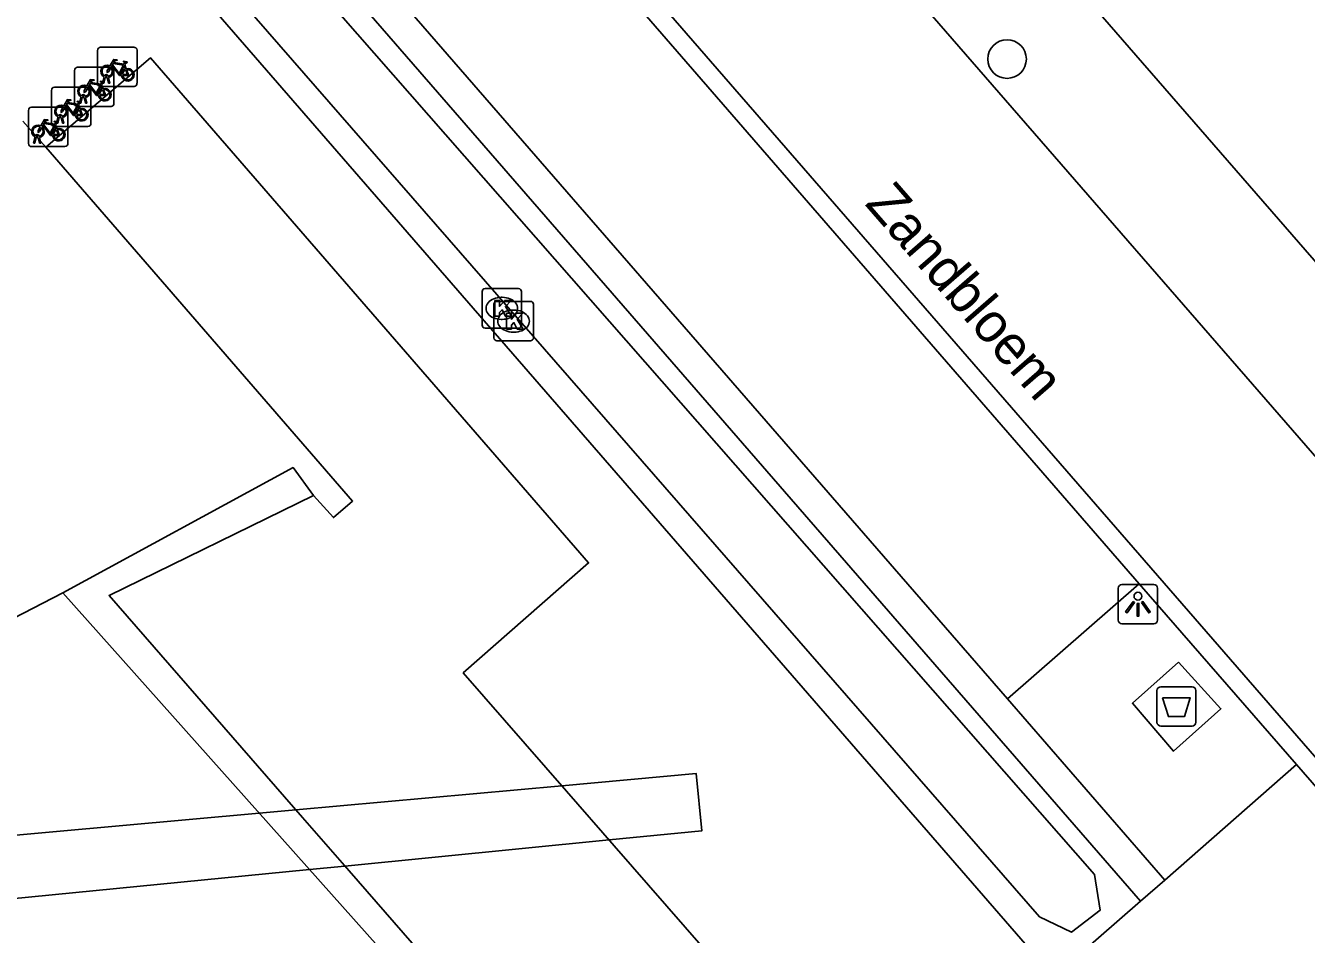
# Model space of a CAD drawing. Extents: x 155888 to 156864, y 383882 to 384671.
# Drawn here: x 156308.74 to 156341.24, y 384016.55 to 384039.61 of the extents above; entities that cross this region are included whole.
import ezdxf

# ---------------------------------------------------------------- set-up
doc = ezdxf.new("R2010")
doc.units = 0
for name, color, linetype in [('IMGEO_Afval_apart_plaats', 7, 'Continuous'), ('IMGEO_Boom', 7, 'Continuous'), ('IMGEO_Dek', 7, 'Continuous'), ('IMGEO_Fietsenrek', 7, 'Continuous'), ('IMGEO_Greppel_droge_sloot', 7, 'Continuous'), ('IMGEO_Kolk', 7, 'Continuous'), ('IMGEO_Lichtpunt', 7, 'Continuous'), ('IMGEO_Muur', 7, 'Continuous'), ('IMGEO_Openbare_ruimte_label', 7, 'Continuous'), ('IMGEO_Pand', 7, 'Continuous'), ('IMGEO_Rijbaan_lokaal_gesloten', 7, 'Continuous'), ('IMGEO_Rijbaan_lokaal_open', 7, 'Continuous'), ('IMGEO_Voetpad_gesloten', 7, 'Continuous'), ('IMGEO_Voetpad_op_trap', 7, 'Continuous'), ('IMGEO_Voetpad_open', 7, 'Continuous')]:
    doc.layers.add(name, color=color, linetype=linetype)

msp = doc.modelspace()

# ---------------------------------------------------------------- linework, layer by layer
at = {"layer": 'IMGEO_Afval_apart_plaats'}
for p, q in [((156337.444, 384021.934), (156337.444, 384022.734)), ((156337.444, 384022.734), (156337.444, 384021.934)), ((156337.544, 384022.834), (156338.334, 384022.834)), ((156338.334, 384022.834), (156337.544, 384022.834)), ((156338.434, 384022.734), (156338.434, 384021.934)), ((156338.434, 384021.934), (156338.434, 384022.734)), ((156338.334, 384021.834), (156337.544, 384021.834)), ((156337.544, 384021.834), (156338.334, 384021.834))]:
    msp.add_line(p, q, dxfattribs=at)
msp.add_lwpolyline([(156337.587, 384022.548), (156338.291, 384022.548), (156338.142, 384022.078), (156337.736, 384022.078), (156337.587, 384022.548)], dxfattribs=at)
for centre, start, end in [((156337.544, 384022.734), 90, 180), ((156337.544, 384022.734), 90, 180), ((156338.334, 384022.734), 0, 90), ((156338.334, 384022.734), 360, 90), ((156337.544, 384021.934), 180, 270), ((156337.544, 384021.934), 180, 270), ((156338.334, 384021.934), 270, 0), ((156338.334, 384021.934), 270, 0)]:
    msp.add_arc(centre, 0.1, start, end, dxfattribs=at)
at = {"layer": 'IMGEO_Boom'}
msp.add_circle((156333.642, 384038.757), 0.489, dxfattribs=at)
at = {"layer": 'IMGEO_Dek'}
msp.add_lwpolyline([(156307.645, 384018.989), (156307.772, 384017.39), (156315.941, 384018.196), (156316.839, 384018.284), (156323.542, 384018.946), (156325.9, 384019.178), (156325.757, 384020.632), (156322.341, 384020.322), (156315.596, 384019.71), (156314.665, 384019.626)], close=True, dxfattribs=at)
at = {"layer": 'IMGEO_Fietsenrek'}
for p, q in [((156310.566, 384038.133), (156310.566, 384038.974)), ((156310.566, 384038.974), (156310.566, 384038.133)), ((156310.641, 384039.058), (156311.482, 384039.058)), ((156311.482, 384039.058), (156310.641, 384039.058)), ((156311.566, 384038.983), (156311.566, 384038.142)), ((156311.566, 384038.142), (156311.566, 384038.983)), ((156309.982, 384037.626), (156309.982, 384038.467)), ((156309.982, 384038.467), (156309.982, 384037.626)), ((156310.057, 384038.551), (156310.898, 384038.551)), ((156310.898, 384038.551), (156310.057, 384038.551)), ((156310.982, 384038.476), (156310.982, 384037.635)), ((156310.982, 384037.635), (156310.982, 384038.476)), ((156311.253, 384038.607), (156311.289, 384038.512)), ((156310.693, 384038.142), (156310.732, 384038.302)), ((156310.727, 384038.142), (156310.693, 384038.142)), ((156310.762, 384038.29), (156310.727, 384038.142)), ((156310.804, 384038.314), (156310.803, 384038.318)), ((156310.845, 384038.142), (156310.811, 384038.284)), ((156310.835, 384038.325), (156310.836, 384038.318)), ((156310.843, 384038.288), (156310.878, 384038.142)), ((156310.878, 384038.142), (156310.845, 384038.142)), ((156309.397, 384037.119), (156309.397, 384037.96)), ((156309.397, 384037.96), (156309.397, 384037.119)), ((156309.472, 384038.044), (156310.313, 384038.044)), ((156310.313, 384038.044), (156309.472, 384038.044)), ((156310.251, 384037.818), (156310.252, 384037.811)), ((156310.397, 384037.969), (156310.397, 384037.128)), ((156310.397, 384037.128), (156310.397, 384037.969)), ((156311.491, 384038.058), (156310.65, 384038.058)), ((156310.65, 384038.058), (156311.491, 384038.058)), ((156310.669, 384038.1), (156310.705, 384038.005)), ((156308.888, 384037.537), (156309.729, 384037.537)), ((156309.729, 384037.537), (156308.888, 384037.537)), ((156310.907, 384037.551), (156310.066, 384037.551)), ((156310.066, 384037.551), (156310.907, 384037.551)), ((156310.084, 384037.593), (156310.12, 384037.498)), ((156310.109, 384037.635), (156310.148, 384037.795)), ((156310.143, 384037.635), (156310.109, 384037.635)), ((156310.178, 384037.783), (156310.143, 384037.635)), ((156310.22, 384037.807), (156310.219, 384037.811)), ((156310.261, 384037.635), (156310.227, 384037.777)), ((156310.259, 384037.781), (156310.294, 384037.635)), ((156310.294, 384037.635), (156310.261, 384037.635)), ((156308.813, 384036.612), (156308.813, 384037.453)), ((156308.813, 384037.453), (156308.813, 384036.612)), ((156309.524, 384037.128), (156309.563, 384037.288)), ((156309.593, 384037.276), (156309.558, 384037.128)), ((156309.635, 384037.3), (156309.634, 384037.304)), ((156309.676, 384037.128), (156309.642, 384037.27)), ((156309.666, 384037.311), (156309.667, 384037.304)), ((156309.674, 384037.274), (156309.709, 384037.128)), ((156309.813, 384037.462), (156309.813, 384036.621)), ((156309.813, 384036.621), (156309.813, 384037.462)), ((156310.322, 384037.044), (156309.481, 384037.044)), ((156309.481, 384037.044), (156310.322, 384037.044)), ((156309.5, 384037.086), (156309.536, 384036.991)), ((156309.558, 384037.128), (156309.524, 384037.128)), ((156309.709, 384037.128), (156309.676, 384037.128)), ((156309.738, 384036.537), (156308.897, 384036.537)), ((156308.897, 384036.537), (156309.738, 384036.537)), ((156308.94, 384036.621), (156308.979, 384036.781)), ((156308.974, 384036.621), (156308.94, 384036.621)), ((156309.009, 384036.769), (156308.974, 384036.621)), ((156309.051, 384036.793), (156309.05, 384036.797)), ((156309.092, 384036.621), (156309.058, 384036.763)), ((156309.082, 384036.804), (156309.083, 384036.797)), ((156309.09, 384036.767), (156309.125, 384036.621)), ((156309.125, 384036.621), (156309.092, 384036.621))]:
    msp.add_line(p, q, dxfattribs=at)
for points in [[(156310.9, 384038.532), (156310.848, 384038.442), (156310.808, 384038.417), (156310.809, 384038.464), (156310.864, 384038.558)], [(156310.879, 384038.584), (156310.974, 384038.748), (156311.06, 384038.734), (156311.062, 384038.725), (156311.006, 384038.714), (156310.979, 384038.669), (156311.235, 384038.628)], [(156311.175, 384038.34), (156311.125, 384038.34), (156310.934, 384038.591), (156310.915, 384038.559)], [(156311.222, 384038.603), (156310.965, 384038.644), (156310.948, 384038.615), (156311.115, 384038.395), (156311.222, 384038.603)], [(156311.27, 384038.505), (156311.24, 384038.582), (156311.131, 384038.364), (156311.174, 384038.364)], [(156311.204, 384038.364), (156311.324, 384038.363), (156311.28, 384038.477)], [(156311.3, 384038.484), (156311.355, 384038.339), (156311.205, 384038.339)], [(156311.235, 384038.628), (156311.26, 384038.677), (156311.254, 384038.681), (156311.231, 384038.685), (156311.219, 384038.692), (156311.218, 384038.695), (156311.22, 384038.7), (156311.315, 384038.685), (156311.317, 384038.675), (156311.307, 384038.662), (156311.295, 384038.656), (156311.281, 384038.662), (156311.253, 384038.607)], [(156310.295, 384038.077), (156310.39, 384038.241), (156310.476, 384038.227), (156310.478, 384038.218), (156310.422, 384038.207), (156310.395, 384038.162), (156310.651, 384038.121)], [(156310.651, 384038.121), (156310.676, 384038.17), (156310.67, 384038.174), (156310.647, 384038.178), (156310.635, 384038.185), (156310.634, 384038.188), (156310.636, 384038.193), (156310.731, 384038.178), (156310.733, 384038.168), (156310.723, 384038.155), (156310.711, 384038.149), (156310.697, 384038.155), (156310.669, 384038.1)], [(156310.316, 384038.025), (156310.264, 384037.935), (156310.224, 384037.91), (156310.225, 384037.957), (156310.28, 384038.051)], [(156310.591, 384037.833), (156310.541, 384037.833), (156310.35, 384038.084), (156310.331, 384038.052)], [(156310.638, 384038.096), (156310.381, 384038.137), (156310.364, 384038.108), (156310.531, 384037.888), (156310.638, 384038.096)], [(156310.686, 384037.998), (156310.656, 384038.075), (156310.547, 384037.857), (156310.59, 384037.857)], [(156310.62, 384037.857), (156310.74, 384037.856), (156310.696, 384037.97)], [(156310.716, 384037.977), (156310.771, 384037.832), (156310.621, 384037.832)], [(156309.731, 384037.518), (156309.679, 384037.428), (156309.639, 384037.403), (156309.64, 384037.45), (156309.695, 384037.544)], [(156309.71, 384037.57), (156309.805, 384037.734), (156309.891, 384037.72), (156309.893, 384037.711), (156309.837, 384037.7), (156309.81, 384037.655), (156310.066, 384037.614)], [(156310.006, 384037.326), (156309.956, 384037.326), (156309.765, 384037.577), (156309.746, 384037.545)], [(156310.053, 384037.589), (156309.796, 384037.63), (156309.779, 384037.601), (156309.946, 384037.381), (156310.053, 384037.589)], [(156310.101, 384037.491), (156310.071, 384037.568), (156309.962, 384037.35), (156310.005, 384037.35)], [(156310.066, 384037.614), (156310.091, 384037.663), (156310.085, 384037.667), (156310.062, 384037.671), (156310.05, 384037.678), (156310.049, 384037.681), (156310.051, 384037.686), (156310.146, 384037.671), (156310.148, 384037.661), (156310.138, 384037.648), (156310.126, 384037.642), (156310.112, 384037.648), (156310.084, 384037.593)], [(156309.126, 384037.063), (156309.221, 384037.227), (156309.307, 384037.213), (156309.309, 384037.204), (156309.253, 384037.193), (156309.226, 384037.148), (156309.482, 384037.107)], [(156309.482, 384037.107), (156309.507, 384037.156), (156309.501, 384037.16), (156309.478, 384037.164), (156309.466, 384037.171), (156309.465, 384037.174), (156309.467, 384037.179), (156309.562, 384037.164), (156309.564, 384037.154), (156309.554, 384037.141), (156309.542, 384037.135), (156309.528, 384037.141), (156309.5, 384037.086)], [(156310.035, 384037.35), (156310.155, 384037.349), (156310.111, 384037.463)], [(156310.131, 384037.47), (156310.186, 384037.325), (156310.036, 384037.325)], [(156309.147, 384037.011), (156309.095, 384036.921), (156309.055, 384036.896), (156309.056, 384036.943), (156309.111, 384037.037)], [(156309.422, 384036.819), (156309.372, 384036.819), (156309.181, 384037.07), (156309.162, 384037.038)], [(156309.469, 384037.082), (156309.212, 384037.123), (156309.195, 384037.094), (156309.362, 384036.874), (156309.469, 384037.082)], [(156309.517, 384036.984), (156309.487, 384037.061), (156309.378, 384036.843), (156309.421, 384036.843)], [(156309.451, 384036.843), (156309.571, 384036.842), (156309.527, 384036.956)], [(156309.547, 384036.963), (156309.602, 384036.818), (156309.452, 384036.818)]]:
    msp.add_lwpolyline(points, dxfattribs=at)
for centre, radius, start, end in [((156310.644, 384038.98), 0.0779, 92.4484, 184.2845), ((156310.644, 384038.98), 0.0779, 92.4484, 184.2845), ((156311.488, 384038.98), 0.0779, 2.4484, 94.2845), ((156311.488, 384038.98), 0.0779, 2.4484, 94.2845), ((156310.06, 384038.473), 0.0779, 92.4484, 184.2845), ((156310.06, 384038.473), 0.0779, 92.4484, 184.2845), ((156310.806, 384038.443), 0.159, 62.6766, 242.1369), ((156310.806, 384038.443), 0.129, 63.3192, 238.903), ((156310.806, 384038.443), 0.129, 283.6043, 43.4302), ((156310.806, 384038.443), 0.159, 283.5766, 46.6042), ((156310.904, 384038.473), 0.0779, 2.4484, 94.2845), ((156310.904, 384038.473), 0.0779, 2.4484, 94.2845), ((156311.333, 384038.359), 0.159, 113.3408, 178.3217), ((156311.333, 384038.359), 0.159, 187.0065, 105.7708), ((156311.333, 384038.359), 0.129, 113.923, 177.9556), ((156311.333, 384038.359), 0.129, 188.6715, 104.5883), ((156310.786, 384038.314), 0.0499, 12.8025, 158.6934), ((156310.806, 384038.443), 0.159, 253.9967, 271.7867), ((156310.786, 384038.314), 0.0174, 12.8025, 163.4502), ((156310.806, 384038.443), 0.129, 253.415, 269.0204), ((156311.488, 384038.136), 0.0779, 272.4484, 4.2845), ((156311.488, 384038.136), 0.0779, 272.4484, 4.2845), ((156309.475, 384037.966), 0.0779, 92.4484, 184.2845), ((156309.475, 384037.966), 0.0779, 92.4484, 184.2845), ((156310.222, 384037.936), 0.159, 62.6766, 242.1369), ((156310.222, 384037.936), 0.129, 63.3192, 238.903), ((156310.202, 384037.807), 0.0499, 12.8025, 158.6934), ((156310.202, 384037.807), 0.0174, 12.8025, 163.4502), ((156310.222, 384037.936), 0.129, 283.6043, 43.4302), ((156310.222, 384037.936), 0.159, 283.5766, 46.6042), ((156310.319, 384037.966), 0.0779, 2.4484, 94.2845), ((156310.319, 384037.966), 0.0779, 2.4484, 94.2845), ((156310.644, 384038.136), 0.0779, 182.4484, 274.2845), ((156310.644, 384038.136), 0.0779, 182.4484, 274.2845), ((156310.749, 384037.852), 0.159, 113.3408, 178.3217), ((156310.749, 384037.852), 0.159, 187.0065, 105.7708), ((156310.749, 384037.852), 0.129, 113.923, 177.9556), ((156310.749, 384037.852), 0.129, 188.6715, 104.5883), ((156308.891, 384037.459), 0.0779, 92.4484, 184.2845), ((156308.891, 384037.459), 0.0779, 92.4484, 184.2845), ((156309.637, 384037.429), 0.159, 62.6766, 242.1369), ((156309.637, 384037.429), 0.129, 63.3192, 238.903), ((156309.637, 384037.429), 0.129, 283.6043, 43.4302), ((156309.637, 384037.429), 0.159, 283.5766, 46.6042), ((156309.735, 384037.459), 0.0779, 2.4484, 94.2845), ((156309.735, 384037.459), 0.0779, 2.4484, 94.2845), ((156310.06, 384037.629), 0.0779, 182.4484, 274.2845), ((156310.06, 384037.629), 0.0779, 182.4484, 274.2845), ((156310.164, 384037.345), 0.159, 113.3408, 178.3217), ((156310.164, 384037.345), 0.159, 187.0065, 105.7708), ((156310.222, 384037.936), 0.159, 253.9967, 271.7867), ((156310.222, 384037.936), 0.129, 253.415, 269.0204), ((156310.904, 384037.629), 0.0779, 272.4484, 4.2845), ((156310.904, 384037.629), 0.0779, 272.4484, 4.2845), ((156309.617, 384037.3), 0.0499, 12.8025, 158.6934), ((156309.637, 384037.429), 0.159, 253.9967, 271.7867), ((156309.617, 384037.3), 0.0174, 12.8025, 163.4502), ((156309.637, 384037.429), 0.129, 253.415, 269.0204), ((156310.164, 384037.345), 0.129, 113.923, 177.9556), ((156310.164, 384037.345), 0.129, 188.6715, 104.5883), ((156309.053, 384036.922), 0.159, 62.6766, 242.1369), ((156309.053, 384036.922), 0.129, 63.3192, 238.903), ((156309.033, 384036.793), 0.0499, 12.8025, 158.6934), ((156309.053, 384036.922), 0.129, 283.6043, 43.4302), ((156309.053, 384036.922), 0.159, 283.5766, 46.6042), ((156309.475, 384037.122), 0.0779, 182.4484, 274.2845), ((156309.475, 384037.122), 0.0779, 182.4484, 274.2845), ((156309.58, 384036.838), 0.159, 113.3408, 178.3217), ((156309.58, 384036.838), 0.159, 187.0065, 105.7708), ((156309.58, 384036.838), 0.129, 113.923, 177.9556), ((156309.58, 384036.838), 0.129, 188.6715, 104.5883), ((156310.319, 384037.122), 0.0779, 272.4484, 4.2845), ((156310.319, 384037.122), 0.0779, 272.4484, 4.2845), ((156308.891, 384036.615), 0.0779, 182.4484, 274.2845), ((156308.891, 384036.615), 0.0779, 182.4484, 274.2845), ((156309.053, 384036.922), 0.159, 253.9967, 271.7867), ((156309.033, 384036.793), 0.0174, 12.8025, 163.4502), ((156309.053, 384036.922), 0.129, 253.415, 269.0204), ((156309.735, 384036.615), 0.0779, 272.4484, 4.2845), ((156309.735, 384036.615), 0.0779, 272.4484, 4.2845)]:
    msp.add_arc(centre, radius, start, end, dxfattribs=at)
at = {"layer": 'IMGEO_Greppel_droge_sloot'}
msp.add_lwpolyline([(156310.286, 384047.24), (156335.861, 384018.073), (156336.002, 384017.163), (156335.275, 384016.608), (156334.468, 384016.994), (156309.059, 384046.139), (156310.286, 384047.24)], dxfattribs=at)
at = {"layer": 'IMGEO_Kolk'}
for p, q in [((156320.321, 384032.007), (156320.321, 384032.859)), ((156320.396, 384032.933), (156321.248, 384032.933)), ((156320.809, 384032.713), (156320.834, 384032.713)), ((156321.322, 384032.859), (156321.322, 384032.007)), ((156320.621, 384031.683), (156320.621, 384032.535)), ((156320.696, 384032.609), (156321.548, 384032.609)), ((156321.109, 384032.389), (156321.134, 384032.389)), ((156321.622, 384032.535), (156321.622, 384031.683)), ((156320.832, 384032.153), (156320.807, 384032.153)), ((156321.248, 384031.933), (156320.396, 384031.933)), ((156321.132, 384031.829), (156321.107, 384031.829)), ((156321.548, 384031.609), (156320.696, 384031.609))]:
    msp.add_line(p, q, dxfattribs=at)
for points in [[(156320.321, 384032.007), (156320.321, 384032.859)], [(156320.396, 384032.933), (156321.248, 384032.933)], [(156320.642, 384032.633), (156320.765, 384032.633), (156320.765, 384032.482), (156320.895, 384032.633), (156321.059, 384032.633), (156320.913, 384032.482), (156321.066, 384032.233), (156320.914, 384032.233), (156320.829, 384032.397), (156320.765, 384032.33), (156320.765, 384032.233), (156320.642, 384032.233), (156320.642, 384032.633)], [(156321.322, 384032.859), (156321.322, 384032.007)], [(156320.621, 384031.683), (156320.621, 384032.535)], [(156320.696, 384032.609), (156321.548, 384032.609)], [(156320.942, 384032.309), (156321.065, 384032.309), (156321.065, 384032.158), (156321.195, 384032.309), (156321.359, 384032.309), (156321.213, 384032.158), (156321.366, 384031.909), (156321.214, 384031.909), (156321.129, 384032.073), (156321.065, 384032.006), (156321.065, 384031.909), (156320.942, 384031.909), (156320.942, 384032.309)], [(156321.622, 384032.535), (156321.622, 384031.683)], [(156321.248, 384031.933), (156320.396, 384031.933)], [(156321.548, 384031.609), (156320.696, 384031.609)]]:
    msp.add_lwpolyline(points, dxfattribs=at)
for centre, start, end in [((156320.398, 384032.857), 91.552, 178.448), ((156320.398, 384032.857), 91.552, 178.448), ((156321.246, 384032.857), 1.552, 88.448), ((156321.246, 384032.857), 1.552, 88.448), ((156320.698, 384032.533), 91.552, 178.448), ((156320.698, 384032.533), 91.552, 178.448), ((156321.546, 384032.533), 1.552, 88.448), ((156321.546, 384032.533), 1.552, 88.448), ((156320.398, 384032.009), 181.552, 268.448), ((156320.398, 384032.009), 181.552, 268.448), ((156321.246, 384032.009), 271.552, 358.448), ((156321.246, 384032.009), 271.552, 358.448), ((156320.698, 384031.685), 181.552, 268.448), ((156320.698, 384031.685), 181.552, 268.448), ((156321.546, 384031.685), 271.552, 358.448), ((156321.546, 384031.685), 271.552, 358.448)]:
    msp.add_arc(centre, 0.0765, start, end, dxfattribs=at)
for centre, major_axis, ratio, start_param, end_param in [((156320.808, 384032.433), (-0.387, 0.002), 0.722429, 4.712389, 7.853982), ((156320.833, 384032.433), (-0.39, 0.002), 0.717154, 1.570796, 4.712389), ((156321.108, 384032.109), (-0.387, 0.002), 0.722429, 4.712389, 7.853982), ((156321.133, 384032.109), (-0.39, 0.002), 0.717154, 1.570796, 4.712389)]:
    msp.add_ellipse(centre, major_axis=major_axis, ratio=ratio, start_param=start_param, end_param=end_param, dxfattribs=at)
at = {"layer": 'IMGEO_Lichtpunt'}
for p, q in [((156336.463, 384025.332), (156336.463, 384024.525)), ((156336.463, 384025.332), (156336.463, 384024.525)), ((156337.365, 384025.427), (156336.557, 384025.427)), ((156337.365, 384025.427), (156336.557, 384025.427)), ((156337.459, 384024.525), (156337.459, 384025.332)), ((156337.459, 384024.525), (156337.459, 384025.332)), ((156336.557, 384024.431), (156337.365, 384024.431)), ((156336.557, 384024.431), (156337.365, 384024.431))]:
    msp.add_line(p, q, dxfattribs=at)
for points in [[(156336.837, 384024.996), (156336.876, 384024.968), (156336.688, 384024.706), (156336.65, 384024.733), (156336.837, 384024.996)], [(156336.939, 384024.948), (156336.986, 384024.948), (156336.986, 384024.626), (156336.939, 384024.626), (156336.939, 384024.948)], [(156337.049, 384024.968), (156337.087, 384024.995), (156337.274, 384024.733), (156337.235, 384024.705), (156337.049, 384024.968)]]:
    msp.add_lwpolyline(points, dxfattribs=at)
msp.add_circle((156336.962, 384025.13), 0.0994, dxfattribs=at)
for centre, start, end in [((156336.557, 384025.332), 90, 180), ((156336.557, 384025.332), 90, 180), ((156337.365, 384025.332), 0, 90), ((156337.365, 384025.332), 0, 90), ((156336.557, 384024.525), 180, 270), ((156336.557, 384024.525), 180, 270), ((156337.365, 384024.525), 270, 0), ((156337.365, 384024.525), 270, 360)]:
    msp.add_arc(centre, 0.0946, start, end, dxfattribs=at)
at = {"layer": 'IMGEO_Muur'}
for points in [[(156316.047, 384027.689), (156310.859, 384025.144), (156315.763, 384019.518), (156316.948, 384018.159), (156326.192, 384007.554)], [(156326.192, 384007.554), (156325.753, 384007.192), (156309.681, 384025.215)]]:
    msp.add_lwpolyline(points, dxfattribs=at)
at = {"layer": 'IMGEO_Pand'}
for points in [[(156309.249, 384036.526), (156308.666, 384037.183)], [(156316.047, 384027.689), (156316.55, 384027.123), (156317.037, 384027.543), (156309.249, 384036.526)], [(156309.681, 384025.215), (156288.569, 384014.304), (156281.129, 384022.863), (156280.825, 384022.622), (156280.395, 384023.106), (156293.888, 384034.824)], [(156309.681, 384025.215), (156315.525, 384028.392), (156316.047, 384027.689)]]:
    msp.add_lwpolyline(points, dxfattribs=at)
at = {"layer": 'IMGEO_Rijbaan_lokaal_gesloten'}
for points in [[(156280.427, 384091.296), (156283.957, 384087.246), (156289.413, 384080.986), (156306.544, 384061.236), (156310.724, 384056.416), (156314.044, 384052.599), (156341.332, 384021.196), (156345.148, 384016.792), (156359.753, 384000), (156367.328, 383991.29), (156368.7, 383989.651), (156369.329, 383988.906)], [(156327.395, 384044.864), (156357.31, 384010.459)]]:
    msp.add_lwpolyline(points, dxfattribs=at)
at = {"layer": 'IMGEO_Rijbaan_lokaal_open'}
for points in [[(156313.707, 384052.278), (156314.932, 384050.866), (156336.989, 384025.442)], [(156336.989, 384025.442), (156340.981, 384020.864)], [(156344.782, 384016.494), (156340.981, 384020.864)]]:
    msp.add_lwpolyline(points, dxfattribs=at)
at = {"layer": 'IMGEO_Voetpad_gesloten'}
msp.add_lwpolyline([(156337.989, 384023.46), (156339.069, 384022.276), (156337.865, 384021.198), (156336.821, 384022.416), (156337.989, 384023.46)], dxfattribs=at)
at = {"layer": 'IMGEO_Voetpad_op_trap'}
msp.add_lwpolyline([(156307.645, 384018.989), (156307.772, 384017.39), (156315.941, 384018.196), (156316.839, 384018.284), (156323.542, 384018.946), (156325.9, 384019.178), (156325.757, 384020.632), (156322.341, 384020.322), (156315.596, 384019.71), (156314.665, 384019.626), (156307.645, 384018.989)], dxfattribs=at)
at = {"layer": 'IMGEO_Voetpad_open'}
for points in [[(156333.649, 384022.524), (156311.573, 384047.941), (156310.33, 384049.351)], [(156328.149, 384048.934), (156360.938, 384011.241)], [(156309.711, 384048.832), (156337.029, 384017.397)], [(156334.824, 384015.476), (156307.48, 384046.967)], [(156309.249, 384036.526), (156311.909, 384038.787), (156323.025, 384025.975), (156319.842, 384023.185), (156322.461, 384020.185), (156323.669, 384018.8), (156330.352, 384011.144), (156330.873, 384011.616), (156333.288, 384008.808), (156332.566, 384008.153), (156333.911, 384006.968), (156334.477, 384007.458), (156339.641, 384001.494)], [(156336.989, 384025.442), (156333.649, 384022.524)], [(156337.644, 384017.927), (156333.649, 384022.524)], [(156340.981, 384020.864), (156337.644, 384017.927)], [(156337.029, 384017.397), (156337.644, 384017.927)], [(156337.029, 384017.397), (156334.824, 384015.476)]]:
    msp.add_lwpolyline(points, dxfattribs=at)

# ---------------------------------------------------------------- texts
at = {"layer": 'IMGEO_Openbare_ruimte_label'}
msp.add_text('Zandbloem', height=1, rotation=310.9865, dxfattribs=at).set_placement((156330.012, 384035.075))

doc.saveas('drawing.dxf')
